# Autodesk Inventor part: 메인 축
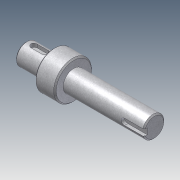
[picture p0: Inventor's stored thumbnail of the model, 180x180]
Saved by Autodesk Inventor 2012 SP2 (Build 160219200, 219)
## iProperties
Company: 한국ATC센터
Created: 2014-10
Part Number: 메인 축
Document SubType Name: Modeling
Designer: KYOUNG IL JANG
Density: 1 g/cm^3
Mass: 29.2926 g
Surface Area: 74.3518 cm^2
Volume: 29.2926 cm^3
Material: 기본값
Author: KYOUNG IL JANG
Revision Number: 1
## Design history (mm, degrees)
sketch "스케치1"
  geometry: L1 (10.497, -57.5)-(112.497, -57.5); L2 (10.497, -66)-(32.497, -66); L3 (32.497, -72.5)-(46.5, -72.5); L4 (46.5, -66)-(112.497, -66); L5 (112.497, -66)-(112.497, -57.5); L6 (10.497, -66)-(10.497, -57.5); L7 (46.5, -69.749)-(46.5, -45.251) reference; L8 (46.5, -72.5)-(46.5, -66); L9 (32.497, -72.5)-(32.497, -66); L10 (32.497, -35)-(32.497, -80) reference; 3 further points
  constraints: 16 end point, 3 point on line, 2 parallel, 2 perpendicular, 1 collinear, 1 horizontal, 1 midpoint
  dimensions: "d0" = 17 diameter of L4 L1; "d1" = 30 diameter of L3 L1; "d2" = 22 distance of L2.start L2.end; "d3" = 65.99692 distance of L4.start L4.end (derived); "d5" = 17 diameter of L2 L1; "d19" = 80 distance between parallel lines of L5 L9
revolve "회전1" sketch "스케치1" stored, may be unused: angle "d4" = 90 deg
chamfer "모따기1" distance "d6" = 1; stored, may be unused: second distance "d7" = 2, angle "d8" = 45 deg
node "작업 평면1"
sketch "스케치2"
  geometry: L1 (-11, -7.5)-(-11, 7.5) reference; L2 (-4.5, 2.5)-(4.5, 2.5); L3 (4.5, -2.5)-(-4.5, -2.5); A1 r 2.5 centre (4.5, 0) between (4.5, -2.5) and (4.5, 2.5); A2 r 2.5 centre (-4.5, 0) between (-4.5, 2.5) and (-4.5, -2.5); 2 further points
  constraints: 4 end point, 4 point on circle, 4 tangent, 2 centre point, 1 horizontal alignment, 1 midpoint, 1 parallel, 1 perpendicular
  dimensions: "d9" = 5 distance between parallel lines of L3 L2; "d10" = 14 dimension on A1 A2; "d11" = 4 distance edge to line of A2 L1
extrude "돌출1" cut sketch "스케치2" distance "d12" = 3; taper "d13" = 0 deg
node "작업 평면2"
sketch "스케치3"
  geometry: L1 (32.998, 7.5)-(32.998, -7.5) reference; L2 (32.998, 2.5)-(17.498, 2.5); L3 (17.498, -2.5)-(32.998, -2.5); A1 r 2.5 centre (17.498, 0) between (17.498, 2.5) and (17.498, -2.5); 2 further points
  constraints: 4 end point, 2 perpendicular, 2 point on circle, 2 point on line, 2 tangent, 1 centre point, 1 horizontal alignment, 1 midpoint
  dimensions: "d14" = 5 distance between parallel lines of L3 L2; "d15" = 18 dimension on A1 L1
extrude "돌출2" cut sketch "스케치3" distance "d16" = 3; taper "d17" = 0 deg
node "솔리드1"
node "참조4"
node "참조5"
